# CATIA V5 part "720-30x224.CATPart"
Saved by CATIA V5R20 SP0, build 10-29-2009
Part number: 720-30x224
Definition: NONE
Nomenclature: 720-30x224
Source: Unknown
Description: 720-30x224
Bounding box of the stored display mesh (mm): x 0 to 224, y -15 to 15, z -15 to 15
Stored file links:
  C:\Users\Utente\Desktop\IO LAVORO\3D X SITO CF\X SITO\720\720-30x224.CATPart
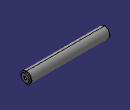
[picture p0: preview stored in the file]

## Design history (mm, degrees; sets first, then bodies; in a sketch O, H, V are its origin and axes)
Body1 "720-30x224" (main body)
  Solid1: solid without history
